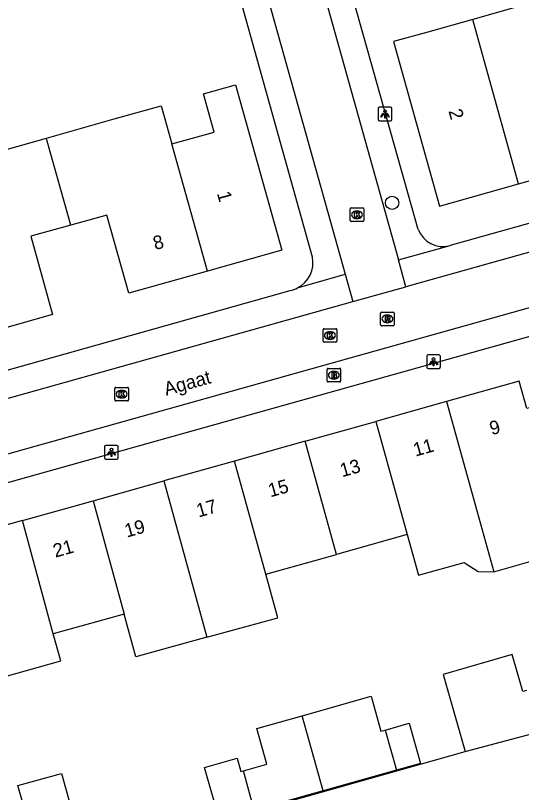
# Model space of a CAD drawing. Extents: x 159628 to 160723, y 388176 to 389416.
# Drawn here: x 159914.3 to 159951.4, y 388311.2 to 388368.2 of the extents above; entities that cross this region are included whole.
import ezdxf

# ---------------------------------------------------------------- set-up
doc = ezdxf.new("R2010")
doc.units = 0
for name, color, linetype in [('IMGEO_Boom', 7, 'Continuous'), ('IMGEO_Brandkraan', 7, 'Continuous'), ('IMGEO_Kolk', 7, 'Continuous'), ('IMGEO_Lichtpunt', 7, 'Continuous'), ('IMGEO_Openbare_ruimte_label', 7, 'Continuous'), ('IMGEO_Pand', 7, 'Continuous'), ('IMGEO_Pand_nummerreeks', 7, 'Continuous'), ('IMGEO_Rijbaan_lokaal_open', 7, 'Continuous'), ('IMGEO_Rioolput', 7, 'Continuous'), ('IMGEO_Voetpad_open', 7, 'Continuous')]:
    doc.layers.add(name, color=color, linetype=linetype)

msp = doc.modelspace()

# ---------------------------------------------------------------- linework, layer by layer
at = {"layer": 'IMGEO_Boom'}
msp.add_circle((159941.947, 388354.433), 0.489, dxfattribs=at)
at = {"layer": 'IMGEO_Brandkraan'}
for p, q in [((159937.167, 388341.36), (159937.167, 388342.212)), ((159937.242, 388342.286), (159938.094, 388342.286)), ((159937.655, 388342.066), (159937.68, 388342.066)), ((159938.168, 388342.212), (159938.168, 388341.36)), ((159937.678, 388341.506), (159937.653, 388341.506)), ((159938.094, 388341.286), (159937.242, 388341.286))]:
    msp.add_line(p, q, dxfattribs=at)
for points in [[(159937.167, 388341.36), (159937.167, 388342.212)], [(159937.242, 388342.286), (159938.094, 388342.286)], [(159938.168, 388342.212), (159938.168, 388341.36)], [(159937.515, 388341.986), (159937.515, 388341.586), (159937.728, 388341.586)], [(159937.746, 388341.986), (159937.515, 388341.986)], [(159937.694, 388341.905), (159937.64, 388341.905), (159937.64, 388341.829)], [(159937.64, 388341.829), (159937.693, 388341.829)], [(159937.702, 388341.753), (159937.64, 388341.753), (159937.64, 388341.672)], [(159937.64, 388341.672), (159937.702, 388341.672)], [(159938.094, 388341.286), (159937.242, 388341.286)]]:
    msp.add_lwpolyline(points, dxfattribs=at)
for centre, radius, start, end in [((159937.244, 388342.21), 0.0765, 91.552, 178.448), ((159937.244, 388342.21), 0.0765, 91.552, 178.448), ((159938.092, 388342.21), 0.0765, 1.552, 88.448), ((159938.092, 388342.21), 0.0765, 1.552, 88.448), ((159937.695, 388341.867), 0.0379, 267.8285, 90.9355), ((159937.703, 388341.712), 0.0404, 269.8759, 90.5077), ((159937.734, 388341.837), 0.251, 268.6676, 293.5347), ((159937.75, 388341.841), 0.145, 59.4692, 91.5367), ((159937.775, 388341.888), 0.0922, 285.5137, 58.1501), ((159937.78, 388341.696), 0.105, 301.3115, 78.989), ((159937.244, 388341.362), 0.0765, 181.552, 268.448), ((159937.244, 388341.362), 0.0765, 181.552, 268.448), ((159938.092, 388341.362), 0.0765, 271.552, 358.448), ((159938.092, 388341.362), 0.0765, 271.552, 358.448)]:
    msp.add_arc(centre, radius, start, end, dxfattribs=at)
for centre, major_axis, ratio, start_param, end_param in [((159937.654, 388341.786), (-0.387, 0.002), 0.722429, 4.712389, 7.853982), ((159937.679, 388341.786), (-0.39, 0.002), 0.717154, 1.570796, 4.712389)]:
    msp.add_ellipse(centre, major_axis=major_axis, ratio=ratio, start_param=start_param, end_param=end_param, dxfattribs=at)
at = {"layer": 'IMGEO_Kolk'}
for p, q in [((159938.945, 388354.062), (159939.797, 388354.062)), ((159938.87, 388353.136), (159938.87, 388353.988)), ((159939.358, 388353.842), (159939.383, 388353.842)), ((159939.871, 388353.988), (159939.871, 388353.136)), ((159939.797, 388353.062), (159938.945, 388353.062)), ((159939.381, 388353.282), (159939.356, 388353.282)), ((159936.878, 388344.272), (159936.878, 388345.124)), ((159936.953, 388345.198), (159937.805, 388345.198)), ((159937.366, 388344.978), (159937.391, 388344.978)), ((159937.879, 388345.124), (159937.879, 388344.272)), ((159937.389, 388344.418), (159937.364, 388344.418)), ((159937.805, 388344.198), (159936.953, 388344.198)), ((159921.583, 388339.964), (159921.583, 388340.816)), ((159921.658, 388340.89), (159922.51, 388340.89)), ((159922.071, 388340.67), (159922.096, 388340.67)), ((159922.584, 388340.816), (159922.584, 388339.964)), ((159922.51, 388339.89), (159921.658, 388339.89)), ((159922.094, 388340.11), (159922.069, 388340.11))]:
    msp.add_line(p, q, dxfattribs=at)
for points in [[(159938.945, 388354.062), (159939.797, 388354.062)], [(159938.87, 388353.136), (159938.87, 388353.988)], [(159939.191, 388353.762), (159939.314, 388353.762), (159939.314, 388353.611), (159939.444, 388353.762), (159939.608, 388353.762), (159939.462, 388353.611), (159939.615, 388353.362), (159939.463, 388353.362), (159939.378, 388353.526), (159939.314, 388353.459), (159939.314, 388353.362), (159939.191, 388353.362), (159939.191, 388353.762)], [(159939.871, 388353.988), (159939.871, 388353.136)], [(159939.797, 388353.062), (159938.945, 388353.062)], [(159936.878, 388344.272), (159936.878, 388345.124)], [(159936.953, 388345.198), (159937.805, 388345.198)], [(159937.879, 388345.124), (159937.879, 388344.272)], [(159937.199, 388344.898), (159937.322, 388344.898), (159937.322, 388344.747), (159937.452, 388344.898), (159937.616, 388344.898), (159937.47, 388344.747), (159937.623, 388344.498), (159937.471, 388344.498), (159937.386, 388344.662), (159937.322, 388344.595), (159937.322, 388344.498), (159937.199, 388344.498), (159937.199, 388344.898)], [(159937.805, 388344.198), (159936.953, 388344.198)], [(159921.583, 388339.964), (159921.583, 388340.816)], [(159921.658, 388340.89), (159922.51, 388340.89)], [(159921.904, 388340.59), (159922.027, 388340.59), (159922.027, 388340.439), (159922.157, 388340.59), (159922.321, 388340.59), (159922.175, 388340.439), (159922.328, 388340.19), (159922.176, 388340.19), (159922.091, 388340.354), (159922.027, 388340.287), (159922.027, 388340.19), (159921.904, 388340.19), (159921.904, 388340.59)], [(159922.584, 388340.816), (159922.584, 388339.964)], [(159922.51, 388339.89), (159921.658, 388339.89)]]:
    msp.add_lwpolyline(points, dxfattribs=at)
for centre, start, end in [((159938.947, 388353.986), 91.552, 178.448), ((159938.947, 388353.986), 91.552, 178.448), ((159939.795, 388353.986), 1.552, 88.448), ((159939.795, 388353.986), 1.552, 88.448), ((159938.947, 388353.138), 181.552, 268.448), ((159938.947, 388353.138), 181.552, 268.448), ((159939.795, 388353.138), 271.552, 358.448), ((159939.795, 388353.138), 271.552, 358.448), ((159936.955, 388345.122), 91.552, 178.448), ((159936.955, 388345.122), 91.552, 178.448), ((159937.803, 388345.122), 1.552, 88.448), ((159937.803, 388345.122), 1.552, 88.448), ((159936.955, 388344.274), 181.552, 268.448), ((159936.955, 388344.274), 181.552, 268.448), ((159937.803, 388344.274), 271.552, 358.448), ((159937.803, 388344.274), 271.552, 358.448), ((159921.66, 388340.814), 91.552, 178.448), ((159921.66, 388340.814), 91.552, 178.448), ((159922.508, 388340.814), 1.552, 88.448), ((159922.508, 388340.814), 1.552, 88.448), ((159921.66, 388339.966), 181.552, 268.448), ((159921.66, 388339.966), 181.552, 268.448), ((159922.508, 388339.966), 271.552, 358.448), ((159922.508, 388339.966), 271.552, 358.448)]:
    msp.add_arc(centre, 0.0765, start, end, dxfattribs=at)
for centre, major_axis, ratio, start_param, end_param in [((159939.357, 388353.562), (-0.387, 0.002), 0.722429, 4.712389, 7.853982), ((159939.382, 388353.562), (-0.39, 0.002), 0.717154, 1.570796, 4.712389), ((159937.365, 388344.698), (-0.387, 0.002), 0.722429, 4.712389, 7.853982), ((159937.39, 388344.698), (-0.39, 0.002), 0.717154, 1.570796, 4.712389), ((159922.07, 388340.39), (-0.387, 0.002), 0.722429, 4.712389, 7.853982), ((159922.095, 388340.39), (-0.39, 0.002), 0.717154, 1.570796, 4.712389)]:
    msp.add_ellipse(centre, major_axis=major_axis, ratio=ratio, start_param=start_param, end_param=end_param, dxfattribs=at)
at = {"layer": 'IMGEO_Lichtpunt'}
for p, q in [((159940.928, 388361.354), (159940.928, 388360.547)), ((159940.928, 388361.354), (159940.928, 388360.547)), ((159941.83, 388361.449), (159941.022, 388361.449)), ((159941.83, 388361.449), (159941.022, 388361.449)), ((159941.924, 388360.547), (159941.924, 388361.354)), ((159941.924, 388360.547), (159941.924, 388361.354)), ((159941.022, 388360.453), (159941.83, 388360.453)), ((159941.022, 388360.453), (159941.83, 388360.453)), ((159945.397, 388343.269), (159944.589, 388343.269)), ((159945.397, 388343.269), (159944.589, 388343.269)), ((159944.495, 388343.174), (159944.495, 388342.367)), ((159944.495, 388343.174), (159944.495, 388342.367)), ((159945.491, 388342.367), (159945.491, 388343.174)), ((159945.491, 388342.367), (159945.491, 388343.174)), ((159944.589, 388342.273), (159945.397, 388342.273)), ((159944.589, 388342.273), (159945.397, 388342.273)), ((159920.831, 388336.531), (159920.831, 388335.724)), ((159920.831, 388336.531), (159920.831, 388335.724)), ((159921.733, 388336.626), (159920.925, 388336.626)), ((159921.733, 388336.626), (159920.925, 388336.626)), ((159921.827, 388335.724), (159921.827, 388336.531)), ((159921.827, 388335.724), (159921.827, 388336.531)), ((159920.925, 388335.63), (159921.733, 388335.63)), ((159920.925, 388335.63), (159921.733, 388335.63))]:
    msp.add_line(p, q, dxfattribs=at)
for points in [[(159941.302, 388361.018), (159941.341, 388360.99), (159941.153, 388360.728), (159941.115, 388360.755), (159941.302, 388361.018)], [(159941.404, 388360.97), (159941.451, 388360.97), (159941.451, 388360.648), (159941.404, 388360.648), (159941.404, 388360.97)], [(159941.514, 388360.99), (159941.552, 388361.017), (159941.739, 388360.755), (159941.7, 388360.727), (159941.514, 388360.99)], [(159944.869, 388342.838), (159944.908, 388342.81), (159944.72, 388342.548), (159944.682, 388342.575), (159944.869, 388342.838)], [(159944.971, 388342.79), (159945.018, 388342.79), (159945.018, 388342.468), (159944.971, 388342.468), (159944.971, 388342.79)], [(159945.081, 388342.81), (159945.119, 388342.837), (159945.306, 388342.575), (159945.267, 388342.547), (159945.081, 388342.81)], [(159921.205, 388336.195), (159921.244, 388336.167), (159921.056, 388335.905), (159921.018, 388335.932), (159921.205, 388336.195)], [(159921.307, 388336.147), (159921.354, 388336.147), (159921.354, 388335.825), (159921.307, 388335.825), (159921.307, 388336.147)], [(159921.417, 388336.167), (159921.455, 388336.194), (159921.642, 388335.932), (159921.603, 388335.904), (159921.417, 388336.167)]]:
    msp.add_lwpolyline(points, dxfattribs=at)
for centre in [(159941.427, 388361.152), (159944.994, 388342.972), (159921.33, 388336.329)]:
    msp.add_circle(centre, 0.0994, dxfattribs=at)
for centre, start, end in [((159941.022, 388361.354), 90, 180), ((159941.022, 388361.354), 90, 180), ((159941.83, 388361.354), 0, 90), ((159941.83, 388361.354), 0, 90), ((159941.022, 388360.547), 180, 270), ((159941.022, 388360.547), 180, 270), ((159941.83, 388360.547), 270, 0), ((159941.83, 388360.547), 270, 360), ((159944.589, 388343.174), 90, 180), ((159944.589, 388343.174), 90, 180), ((159945.397, 388343.174), 0, 90), ((159945.397, 388343.174), 0, 90), ((159944.589, 388342.367), 180, 270), ((159944.589, 388342.367), 180, 270), ((159945.397, 388342.367), 270, 0), ((159945.397, 388342.367), 270, 360), ((159920.925, 388336.531), 90, 180), ((159920.925, 388336.531), 90, 180), ((159921.733, 388336.531), 0, 90), ((159921.733, 388336.531), 0, 90), ((159920.925, 388335.724), 180, 270), ((159920.925, 388335.724), 180, 270), ((159921.733, 388335.724), 270, 0), ((159921.733, 388335.724), 270, 360)]:
    msp.add_arc(centre, 0.0946, start, end, dxfattribs=at)
at = {"layer": 'IMGEO_Pand'}
for points in [[(159956.199, 388370.225), (159951.07, 388368.79), (159947.871, 388367.895)], [(159947.871, 388367.895), (159944.565, 388366.971), (159942.039, 388366.264), (159945.416, 388354.199), (159951.229, 388355.826)], [(159951.229, 388355.826), (159948.704, 388364.888), (159947.871, 388367.895)], [(159951.229, 388355.826), (159956.674, 388357.35), (159955.062, 388363.085), (159957.975, 388363.904)], [(159925.771, 388358.757), (159928.868, 388359.627), (159928.083, 388362.428), (159930.441, 388363.091), (159933.85, 388350.952), (159928.383, 388349.418)], [(159916.565, 388359.193), (159921.545, 388360.592), (159924.992, 388361.56), (159925.771, 388358.757)], [(159908.969, 388354.039), (159912.029, 388354.899), (159911.243, 388357.699), (159916.565, 388359.193)], [(159918.362, 388352.806), (159916.624, 388358.973), (159916.565, 388359.193)], [(159928.383, 388349.418), (159925.771, 388358.757)], [(159928.383, 388349.418), (159922.604, 388347.797), (159921.007, 388353.541), (159918.362, 388352.806)], [(159918.362, 388352.806), (159915.408, 388351.985), (159917.003, 388346.239), (159911.566, 388344.708)], [(159952.024, 388339.382), (159951.845, 388339.332), (159951.278, 388341.345), (159945.951, 388339.851)], [(159945.951, 388339.851), (159940.742, 388338.39)], [(159945.951, 388339.851), (159948.314, 388331.313), (159949.408, 388327.352)], [(159935.572, 388336.94), (159940.742, 388338.39)], [(159940.742, 388338.39), (159943.053, 388330.083)], [(159935.572, 388336.94), (159930.363, 388335.479)], [(159937.874, 388328.631), (159935.572, 388336.94)], [(159930.363, 388335.479), (159925.183, 388334.026)], [(159932.666, 388327.17), (159930.363, 388335.479)], [(159919.993, 388332.571), (159925.183, 388334.026)], [(159925.183, 388334.026), (159927.531, 388325.487), (159928.338, 388322.551)], [(159914.802, 388331.115), (159919.993, 388332.571)], [(159919.993, 388332.571), (159922.271, 388324.255)], [(159914.802, 388331.115), (159909.632, 388329.665), (159909.101, 388329.516), (159909.664, 388327.512)], [(159917.064, 388322.794), (159914.802, 388331.115)], [(159943.053, 388330.083), (159937.874, 388328.631)], [(159943.053, 388330.083), (159943.875, 388327.106), (159947.232, 388328.032), (159948.269, 388327.383), (159949.408, 388327.352)], [(159932.666, 388327.17), (159937.874, 388328.631)], [(159949.408, 388327.352), (159954.399, 388328.773)], [(159928.338, 388322.551), (159933.543, 388323.982), (159932.666, 388327.17)], [(159922.271, 388324.255), (159917.064, 388322.794)], [(159928.338, 388322.551), (159923.128, 388321.119), (159922.271, 388324.255)], [(159911.988, 388319.239), (159912.438, 388319.366), (159912.55, 388319.398), (159917.61, 388320.824), (159917.064, 388322.794)], [(159951.814, 388318.64), (159951.538, 388318.563), (159950.757, 388321.273), (159945.687, 388319.812), (159947.315, 388314.161)], [(159935.341, 388316.79), (159940.404, 388318.215), (159941.125, 388315.65), (159941.446, 388315.74)], [(159931.031, 388312.752), (159932.738, 388313.232), (159932.001, 388315.85), (159935.341, 388316.79)], [(159936.89, 388311.284), (159935.341, 388316.79)], [(159941.446, 388315.74), (159943.208, 388316.233), (159944.033, 388313.292), (159942.262, 388312.794)], [(159941.446, 388315.74), (159942.262, 388312.794)], [(159947.315, 388314.161), (159952.657, 388315.588)], [(159931.827, 388309.859), (159929.259, 388309.136), (159928.176, 388312.987), (159930.573, 388313.662), (159930.832, 388312.696), (159931.031, 388312.752)], [(159921.356, 388307.007), (159916.173, 388305.554), (159914.868, 388310.215), (159914.463, 388311.659), (159917.659, 388312.555), (159918.544, 388309.396), (159920.553, 388309.959)], [(159931.827, 388309.859), (159931.031, 388312.752)], [(159942.262, 388312.794), (159936.89, 388311.284)], [(159936.89, 388311.284), (159933.55, 388310.344), (159931.827, 388309.859)]]:
    msp.add_lwpolyline(points, dxfattribs=at)
at = {"layer": 'IMGEO_Rijbaan_lokaal_open'}
for points in [[(159926.792, 388406.01), (159942.411, 388350.247)], [(159922.879, 388404.913), (159938.495, 388349.196)], [(159952.912, 388351.064), (159942.965, 388348.27)], [(159942.965, 388348.27), (159942.411, 388350.247)], [(159938.495, 388349.196), (159939.056, 388347.194)], [(159939.056, 388347.194), (159942.965, 388348.27)], [(159953.939, 388347.275), (159902.417, 388332.825)], [(159901.439, 388336.64), (159939.056, 388347.194)], [(159893.047, 388296.039), (159893.76, 388296.24), (159895.193, 388299.636), (159898.582, 388300.586), (159898.627, 388300.424), (159947.315, 388314.161)]]:
    msp.add_lwpolyline(points, dxfattribs=at)
at = {"layer": 'IMGEO_Rioolput'}
for p, q in [((159941.104, 388345.489), (159941.104, 388346.341)), ((159941.179, 388346.415), (159942.031, 388346.415)), ((159941.592, 388346.195), (159941.617, 388346.195)), ((159942.105, 388346.341), (159942.105, 388345.489)), ((159941.615, 388345.635), (159941.59, 388345.635)), ((159942.031, 388345.415), (159941.179, 388345.415))]:
    msp.add_line(p, q, dxfattribs=at)
for points in [[(159941.104, 388345.489), (159941.104, 388346.341)], [(159941.179, 388346.415), (159942.031, 388346.415)], [(159941.693, 388346.113), (159941.441, 388346.115), (159941.441, 388345.715)], [(159942.105, 388346.341), (159942.105, 388345.489)], [(159941.441, 388345.715), (159941.565, 388345.715), (159941.565, 388345.877), (159941.576, 388345.877)], [(159941.619, 388346.034), (159941.565, 388346.034), (159941.565, 388345.953)], [(159941.565, 388345.953), (159941.617, 388345.953)], [(159941.623, 388345.848), (159941.694, 388345.715), (159941.834, 388345.715), (159941.769, 388345.841)], [(159942.031, 388345.415), (159941.179, 388345.415)]]:
    msp.add_lwpolyline(points, dxfattribs=at)
for centre, radius, start, end in [((159941.181, 388346.339), 0.0765, 91.552, 178.448), ((159941.181, 388346.339), 0.0765, 91.552, 178.448), ((159941.692, 388346.003), 0.109, 350.3612, 89.416), ((159942.029, 388346.339), 0.0765, 1.552, 88.448), ((159942.029, 388346.339), 0.0765, 1.552, 88.448), ((159941.181, 388345.491), 0.0765, 181.552, 268.448), ((159941.181, 388345.491), 0.0765, 181.552, 268.448), ((159941.575, 388345.824), 0.0533, 26.0293, 88.6989), ((159941.601, 388346.142), 0.19, 274.7715, 282.9687), ((159941.625, 388345.938), 0.0964, 77.0061, 93.1865), ((159941.639, 388345.995), 0.0378, 276.6634, 79.6772), ((159941.69, 388346.003), 0.112, 277.5842, 350.9817), ((159941.674, 388345.788), 0.108, 29.5134, 73.7905), ((159942.029, 388345.491), 0.0765, 271.552, 358.448), ((159942.029, 388345.491), 0.0765, 271.552, 358.448)]:
    msp.add_arc(centre, radius, start, end, dxfattribs=at)
for centre, major_axis, ratio, start_param, end_param in [((159941.591, 388345.915), (-0.387, 0.002), 0.722429, 4.712389, 7.853982), ((159941.616, 388345.915), (-0.39, 0.002), 0.717154, 1.570796, 4.712389)]:
    msp.add_ellipse(centre, major_axis=major_axis, ratio=ratio, start_param=start_param, end_param=end_param, dxfattribs=at)
at = {"layer": 'IMGEO_Voetpad_open'}
for points in [[(159943.86, 388352.486), (159936.09, 388380.029)], [(159936.099, 388350.445), (159928.443, 388377.878)], [(160000.538, 388366.506), (160000, 388366.355), (159946.202, 388351.292)], [(159942.411, 388350.247), (159946.202, 388351.292)], [(159884.421, 388325.702), (159974.2, 388350.834)], [(159935.001, 388348.184), (159938.495, 388349.196)], [(159880.968, 388332.972), (159881.992, 388333.259), (159885.095, 388334.13), (159903.729, 388339.361), (159934.464, 388347.99)]]:
    msp.add_lwpolyline(points, dxfattribs=at)
for centre, radius, start, end in [((159945.697, 388353.196), 1.97, 201.1288, 284.8444), ((159934.02, 388350.058), 2.115, 297.6377, 10.5575), ((159934.012, 388350.081), 2.139, 282.1928, 297.5333)]:
    msp.add_arc(centre, radius, start, end, dxfattribs=at)

# ---------------------------------------------------------------- texts
at = {"layer": 'IMGEO_Openbare_ruimte_label'}
msp.add_text('Agaat', height=1, rotation=15.6621, dxfattribs=at).set_placement((159925.351, 388340.266))
at = {"layer": 'IMGEO_Pand_nummerreeks'}
for s, rotation, p in [('2', 285.637, (159946.079, 388361.178)), ('1', 285.6864, (159929.073, 388355.136)), ('8', 15.6712, (159924.551, 388350.96)), ('9', 15.6647, (159949.263, 388337.373)), ('11', 15.6667, (159943.657, 388335.802)), ('13', 15.6667, (159938.276, 388334.292)), ('15', 15.6667, (159933.004, 388332.814)), ('17', 15.6667, (159927.732, 388331.335)), ('19', 15.6667, (159922.459, 388329.856)), ('21', 15.6667, (159917.208, 388328.384))]:
    msp.add_text(s, height=1, rotation=rotation, dxfattribs=at).set_placement(p)

doc.saveas('drawing.dxf')
